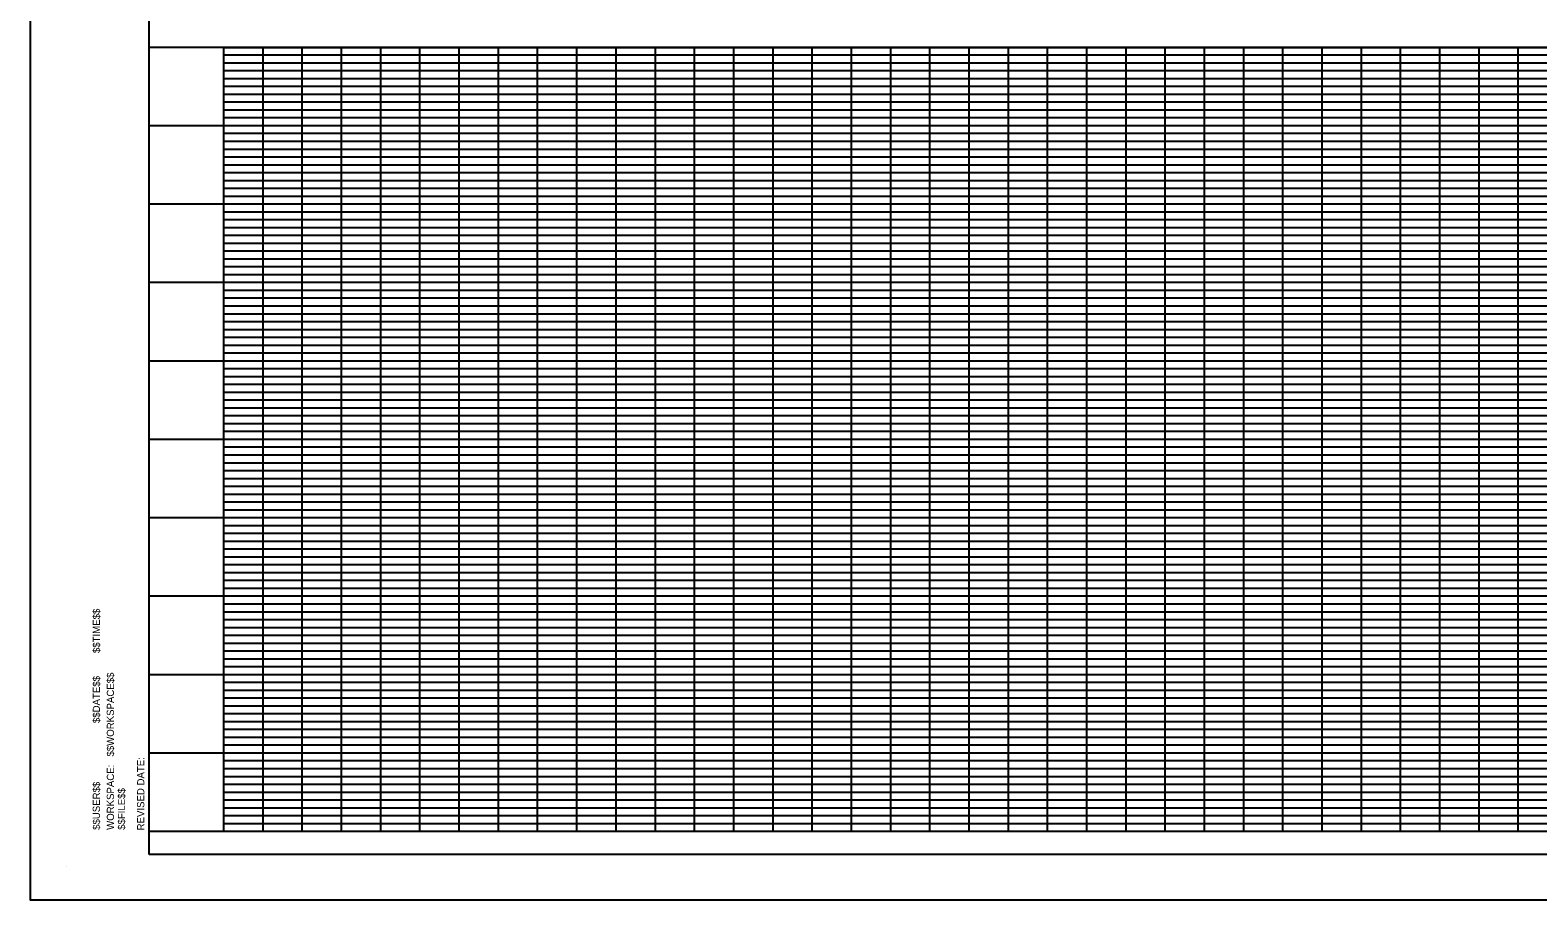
# Model space of a CAD drawing. Extents: x 0 to 19, y -0.6 to 11.2.
# Drawn here: x 0 to 9.61, y 0 to 5.55 of the extents above; entities that cross this region are included whole.
import ezdxf

# ---------------------------------------------------------------- set-up
doc = ezdxf.new("R2010")
doc.units = 0
for name, color, linetype in [('G-ANNO-TEXT', 7, 'Continuous'), ('G-Border-Paper', 7, 'Continuous'), ('G-Border-Sheet', 7, 'Continuous'), ('G-Grid-Border', 7, 'Continuous'), ('G-Grid-Major', 7, 'Continuous'), ('G-Grid-Minor', 7, 'Continuous'), ('G-No Plot-Border-1', 7, 'Continuous'), ('G-No Plot-Border-2', 7, 'Continuous')]:
    doc.layers.add(name, color=color, linetype=linetype)

msp = doc.modelspace()

# ---------------------------------------------------------------- linework, layer by layer
at = {"layer": 'G-ANNO-TEXT'}
msp.add_line((0.234, 0.2139), (0.234, 0.2139), dxfattribs=at)
at = {"layer": 'G-Border-Paper'}
msp.add_lwpolyline([(17, 11), (0, 11), (0, 0), (17, 0)], close=True, dxfattribs=at)
at = {"layer": 'G-Border-Sheet'}
for p, q in [((0.758, 0.2884), (0.758, 10.7116)), ((16.7116, 0.2884), (0.758, 0.2884))]:
    msp.add_line(p, q, dxfattribs=at)
at = {"layer": 'G-Grid-Border'}
for p, q in [((16.7116, 5.4354), (0.758, 5.4354)), ((16.7116, 0.4354), (0.758, 0.4354))]:
    msp.add_line(p, q, dxfattribs=at)
msp.add_lwpolyline([(1.2348, 5.4354), (16.2348, 5.4354), (16.2348, 0.4354), (1.2348, 0.4354)], close=True, dxfattribs=at)
at = {"layer": 'G-Grid-Major'}
for p, q in [((1.7348, 0.4354), (1.7348, 5.4354)), ((2.2348, 0.4354), (2.2348, 5.4354)), ((2.7348, 0.4354), (2.7348, 5.4354)), ((3.2348, 0.4354), (3.2348, 5.4354)), ((3.7348, 0.4354), (3.7348, 5.4354)), ((4.2348, 0.4354), (4.2348, 5.4354)), ((4.7348, 0.4354), (4.7348, 5.4354)), ((5.2348, 0.4354), (5.2348, 5.4354)), ((5.7348, 0.4354), (5.7348, 5.4354)), ((6.2348, 0.4354), (6.2348, 5.4354)), ((6.7348, 0.4354), (6.7348, 5.4354)), ((7.2348, 0.4354), (7.2348, 5.4354)), ((7.7348, 0.4354), (7.7348, 5.4354)), ((8.2348, 0.4354), (8.2348, 5.4354)), ((8.7348, 0.4354), (8.7348, 5.4354)), ((9.2348, 0.4354), (9.2348, 5.4354)), ((16.7116, 4.9354), (0.758, 4.9354)), ((16.7116, 4.4354), (0.758, 4.4354)), ((16.7116, 3.9354), (0.758, 3.9354)), ((16.7116, 3.4354), (0.758, 3.4354)), ((16.7116, 2.9354), (0.758, 2.9354)), ((16.7116, 2.4354), (0.758, 2.4354)), ((16.7116, 1.9354), (0.758, 1.9354)), ((16.7116, 1.4354), (0.758, 1.4354)), ((16.7116, 0.9354), (0.758, 0.9354))]:
    msp.add_line(p, q, dxfattribs=at)
msp.add_lwpolyline([(1.2348, 5.4354), (16.2348, 5.4354), (16.2348, 0.4354), (1.2348, 0.4354)], close=True, dxfattribs=at)
at = {"layer": 'G-Grid-Minor'}
for p, q in [((16.2348, 5.3854), (1.2348, 5.3854)), ((1.4848, 0.4354), (1.4848, 5.4354)), ((1.9848, 0.4354), (1.9848, 5.4354)), ((2.4848, 0.4354), (2.4848, 5.4354)), ((2.9848, 0.4354), (2.9848, 5.4354)), ((3.4848, 0.4354), (3.4848, 5.4354)), ((3.9848, 0.4354), (3.9848, 5.4354)), ((4.4848, 0.4354), (4.4848, 5.4354)), ((4.9848, 0.4354), (4.9848, 5.4354)), ((5.4848, 0.4354), (5.4848, 5.4354)), ((5.9848, 0.4354), (5.9848, 5.4354)), ((6.4848, 0.4354), (6.4848, 5.4354)), ((6.9848, 0.4354), (6.9848, 5.4354)), ((7.4848, 0.4354), (7.4848, 5.4354)), ((7.9848, 0.4354), (7.9848, 5.4354)), ((8.4848, 0.4354), (8.4848, 5.4354)), ((8.9848, 0.4354), (8.9848, 5.4354)), ((9.4848, 0.4354), (9.4848, 5.4354)), ((16.2348, 5.3354), (1.2348, 5.3354)), ((16.2348, 5.2854), (1.2348, 5.2854)), ((16.2348, 5.2354), (1.2348, 5.2354)), ((16.2348, 5.1854), (1.2348, 5.1854)), ((16.2348, 5.1354), (1.2348, 5.1354)), ((16.2348, 5.0854), (1.2348, 5.0854)), ((16.2348, 5.0354), (1.2348, 5.0354)), ((16.2348, 4.9854), (1.2348, 4.9854)), ((16.2348, 4.8854), (1.2348, 4.8854)), ((16.2348, 4.8354), (1.2348, 4.8354)), ((16.2348, 4.7854), (1.2348, 4.7854)), ((16.2348, 4.7354), (1.2348, 4.7354)), ((16.2348, 4.6854), (1.2348, 4.6854)), ((16.2348, 4.6354), (1.2348, 4.6354)), ((16.2348, 4.5854), (1.2348, 4.5854)), ((16.2348, 4.5354), (1.2348, 4.5354)), ((16.2348, 4.4854), (1.2348, 4.4854)), ((16.2348, 4.3854), (1.2348, 4.3854)), ((16.2348, 4.3354), (1.2348, 4.3354)), ((16.2348, 4.2854), (1.2348, 4.2854)), ((16.2348, 4.2354), (1.2348, 4.2354)), ((16.2348, 4.1854), (1.2348, 4.1854)), ((16.2348, 4.1354), (1.2348, 4.1354)), ((16.2348, 4.0854), (1.2348, 4.0854)), ((16.2348, 4.0354), (1.2348, 4.0354)), ((16.2348, 3.9854), (1.2348, 3.9854)), ((16.2348, 3.8854), (1.2348, 3.8854)), ((16.2348, 3.8354), (1.2348, 3.8354)), ((16.2348, 3.7854), (1.2348, 3.7854)), ((16.2348, 3.7354), (1.2348, 3.7354)), ((16.2348, 3.6854), (1.2348, 3.6854)), ((16.2348, 3.6354), (1.2348, 3.6354)), ((16.2348, 3.5854), (1.2348, 3.5854)), ((16.2348, 3.5354), (1.2348, 3.5354)), ((16.2348, 3.4854), (1.2348, 3.4854)), ((16.2348, 3.3854), (1.2348, 3.3854)), ((16.2348, 3.3354), (1.2348, 3.3354)), ((16.2348, 3.2854), (1.2348, 3.2854)), ((16.2348, 3.2354), (1.2348, 3.2354)), ((16.2348, 3.1854), (1.2348, 3.1854)), ((16.2348, 3.1354), (1.2348, 3.1354)), ((16.2348, 3.0854), (1.2348, 3.0854)), ((16.2348, 3.0354), (1.2348, 3.0354)), ((16.2348, 2.9854), (1.2348, 2.9854)), ((16.2348, 2.8854), (1.2348, 2.8854)), ((16.2348, 2.8354), (1.2348, 2.8354)), ((16.2348, 2.7854), (1.2348, 2.7854)), ((16.2348, 2.7354), (1.2348, 2.7354)), ((16.2348, 2.6854), (1.2348, 2.6854)), ((16.2348, 2.6354), (1.2348, 2.6354)), ((16.2348, 2.5854), (1.2348, 2.5854)), ((16.2348, 2.5354), (1.2348, 2.5354)), ((16.2348, 2.4854), (1.2348, 2.4854)), ((16.2348, 2.3854), (1.2348, 2.3854)), ((16.2348, 2.3354), (1.2348, 2.3354)), ((16.2348, 2.2854), (1.2348, 2.2854)), ((16.2348, 2.2354), (1.2348, 2.2354)), ((16.2348, 2.1854), (1.2348, 2.1854)), ((16.2348, 2.1354), (1.2348, 2.1354)), ((16.2348, 2.0854), (1.2348, 2.0854)), ((16.2348, 2.0354), (1.2348, 2.0354)), ((16.2348, 1.9854), (1.2348, 1.9854)), ((16.2348, 1.8854), (1.2348, 1.8854)), ((16.2348, 1.8354), (1.2348, 1.8354)), ((16.2348, 1.7854), (1.2348, 1.7854)), ((16.2348, 1.7354), (1.2348, 1.7354)), ((16.2348, 1.6854), (1.2348, 1.6854)), ((16.2348, 1.6354), (1.2348, 1.6354)), ((16.2348, 1.5854), (1.2348, 1.5854)), ((16.2348, 1.5354), (1.2348, 1.5354)), ((16.2348, 1.4854), (1.2348, 1.4854)), ((16.2348, 1.3854), (1.2348, 1.3854)), ((16.2348, 1.3354), (1.2348, 1.3354)), ((16.2348, 1.2854), (1.2348, 1.2854)), ((16.2348, 1.2354), (1.2348, 1.2354)), ((16.2348, 1.1854), (1.2348, 1.1854)), ((16.2348, 1.1354), (1.2348, 1.1354)), ((16.2348, 1.0854), (1.2348, 1.0854)), ((16.2348, 1.0354), (1.2348, 1.0354)), ((16.2348, 0.9854), (1.2348, 0.9854)), ((16.2348, 0.8854), (1.2348, 0.8854)), ((16.2348, 0.8354), (1.2348, 0.8354)), ((16.2348, 0.7854), (1.2348, 0.7854)), ((16.2348, 0.7354), (1.2348, 0.7354)), ((16.2348, 0.6854), (1.2348, 0.6854)), ((16.2348, 0.6354), (1.2348, 0.6354)), ((16.2348, 0.5854), (1.2348, 0.5854)), ((16.2348, 0.5354), (1.2348, 0.5354)), ((16.2348, 0.4854), (1.2348, 0.4854))]:
    msp.add_line(p, q, dxfattribs=at)
at = {"layer": 'G-No Plot-Border-1'}
msp.add_lwpolyline([(0.758, 5.4354), (0.758, 10.7116), (13.7281, 10.7116), (13.7281, 10.2161), (14.7206, 10.2161), (14.8974, 10.2161), (15.4366, 10.2161), (15.4366, 8.7411), (16.7116, 8.7411), (16.7116, 5.4354)], close=True, dxfattribs=at)
at = {"layer": 'G-No Plot-Border-2'}
msp.add_lwpolyline([(0.758, 5.4354), (0.758, 10.7116), (12.3781, 10.7116), (12.3781, 9.2366), (13.7281, 9.2366), (13.7281, 10.2161), (14.7206, 10.2161), (14.8974, 10.2161), (16.7116, 10.2161), (16.7116, 5.4354)], close=True, dxfattribs=at)

# ---------------------------------------------------------------- texts
at = {"layer": 'G-ANNO-TEXT'}
for s, p in [('$$TIME$$', (0.4448, 1.5736)), ('$$WORKSPACE$$', (0.5343, 0.9137)), ('$$DATE$$', (0.4448, 1.1271)), ('REVISED DATE:', (0.7275, 0.443)), ('WORKSPACE:', (0.5344, 0.4461)), ('$$USER$$', (0.4448, 0.4462)), ('$$FILE$$', (0.6053, 0.4462))]:
    msp.add_text(s, height=0.0459, rotation=90, dxfattribs=at).set_placement(p)

doc.saveas('drawing.dxf')
